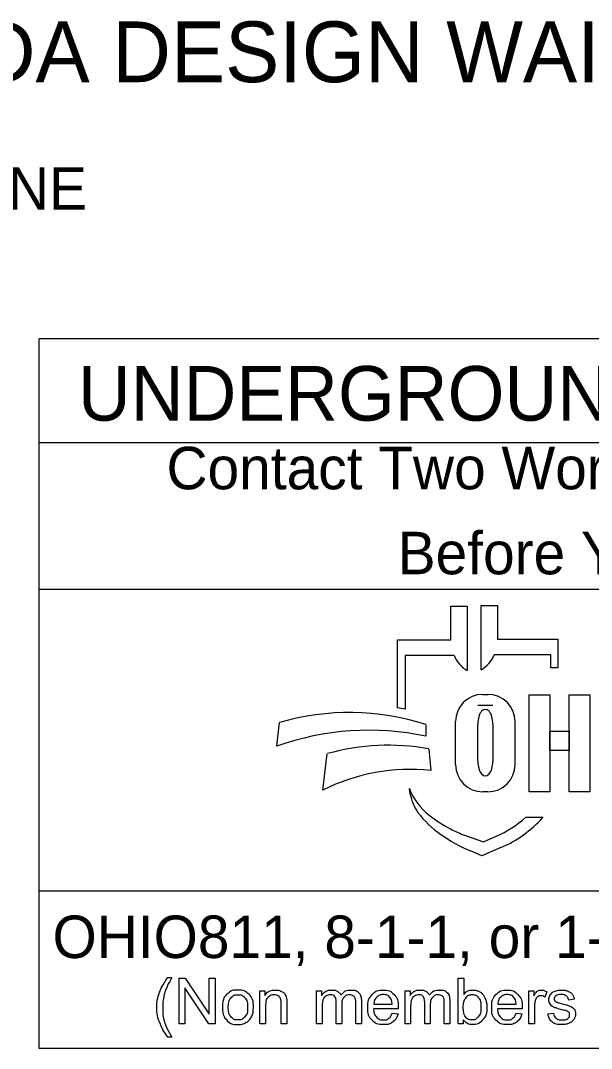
# Model space of a CAD drawing. Extents: x 0 to 34, y 0 to 22.
# Drawn here: x 2.317 to 4.196, y 2.143 to 5.529 of the extents above; entities that cross this region are included whole.
import ezdxf

# ---------------------------------------------------------------- set-up
doc = ezdxf.new("R2010")
doc.units = 0
doc.layers.add('SH_Data', color=7, linetype='Continuous')
doc.layers.add('SH_Text', color=7, linetype='Continuous')

msp = doc.modelspace()

# ---------------------------------------------------------------- linework, layer by layer
at = {"layer": 'SH_Data'}
for p, q in [((2.3775, 2.1428), (2.3775, 4.4803)), ((6.6275, 4.4803), (2.3775, 4.4803)), ((2.3775, 4.1387), (6.6275, 4.1387)), ((2.3775, 3.6553), (6.6275, 3.6553)), ((6.6275, 2.6607), (2.3775, 2.6607)), ((6.6275, 2.1428), (2.3775, 2.1428))]:
    msp.add_line(p, q, dxfattribs=at)
at = {"layer": 'SH_Text'}
for p, q in [((3.7335, 3.4883), (3.7335, 3.5998)), ((3.7335, 3.5998), (3.7872, 3.5998)), ((3.7872, 3.5998), (3.7872, 3.3877)), ((3.8329, 3.39), (3.8329, 3.6021)), ((3.8329, 3.6021), (3.8865, 3.6021)), ((3.8865, 3.6021), (3.8865, 3.4906)), ((3.5576, 3.2644), (3.5576, 3.4883)), ((3.5576, 3.4883), (3.7335, 3.4883)), ((3.8865, 3.4906), (4.0857, 3.4906)), ((4.0857, 3.4906), (4.0857, 3.3968)), ((3.5828, 3.4369), (3.5828, 3.26)), ((3.7439, 3.4369), (3.5828, 3.4369)), ((4.0625, 3.4392), (3.8761, 3.4392)), ((4.0625, 3.3968), (4.0625, 3.4392)), ((4.0857, 3.3968), (4.0625, 3.3968)), ((3.8385, 3.3091), (3.8551, 3.3091)), ((3.8718, 3.2721), (3.822, 3.2721)), ((3.7491, 3.0776), (3.7491, 3.2196)), ((3.9445, 3.2196), (3.9445, 3.0776)), ((3.1602, 3.1381), (3.1696, 3.2162)), ((3.6509, 3.2097), (3.6509, 3.1709)), ((3.822, 3.089), (3.822, 3.2114)), ((3.8718, 3.2114), (3.8718, 3.089)), ((3.6608, 3.1291), (3.6671, 3.0582)), ((3.312, 2.9936), (3.3267, 3.1137)), ((3.5997, 2.9807), (3.5967, 2.9986)), ((3.8551, 2.9882), (3.8385, 2.9882)), ((3.98, 2.9048), (4.0375, 2.9048)), ((3.7816, 2.8444), (3.841, 2.8239)), ((3.841, 2.8239), (3.8821, 2.8417)), ((3.835, 2.7769), (3.7976, 2.7934)), ((3.8983, 2.8044), (3.835, 2.7769))]:
    msp.add_line(p, q, dxfattribs=at)
for points in [[(3.991, 3.3081), (4.0589, 3.3081), (4.0589, 2.9881), (3.991, 2.9881)], [(4.1231, 3.3081), (4.1911, 3.3081), (4.1911, 2.9881), (4.1231, 2.9881)], [(4.0589, 3.1882), (4.1231, 3.1882), (4.1231, 3.1242), (4.0589, 3.1242)]]:
    msp.add_lwpolyline(points, close=True, dxfattribs=at)
for points in [[(2.8021, 2.3766), (2.8153, 2.3766)], [(2.8389, 2.2239), (2.8389, 2.3741), (2.8592, 2.3741), (2.9382, 2.2561), (2.9382, 2.3741), (2.9572, 2.3741), (2.9572, 2.2239), (2.9369, 2.2239), (2.8579, 2.3419), (2.8579, 2.2239), (2.8389, 2.2239)], [(3.7743, 2.2239), (3.7573, 2.2239), (3.7573, 2.3741), (3.7757, 2.3741), (3.7757, 2.3206)], [(3.1048, 2.2239), (3.1048, 2.3328), (3.1214, 2.3328), (3.1214, 2.3173)], [(3.2912, 2.2239), (3.2912, 2.3328), (3.3077, 2.3328), (3.3077, 2.3174)], [(3.5826, 2.2239), (3.5826, 2.3328), (3.5991, 2.3328), (3.5991, 2.3174)], [(3.9904, 2.2239), (3.9904, 2.3328), (4.007, 2.3328), (4.007, 2.3163)], [(4.0495, 2.3293), (4.043, 2.3122)], [(4.1394, 2.3046), (4.1213, 2.3022)], [(3.1233, 2.2833), (3.1233, 2.2239), (3.1048, 2.2239)], [(3.1932, 2.2908), (3.1932, 2.2239), (3.1748, 2.2239), (3.1748, 2.2901)], [(3.3097, 2.2803), (3.3097, 2.2239), (3.2912, 2.2239)], [(3.3743, 2.2871), (3.3743, 2.2239), (3.3559, 2.2239), (3.3559, 2.2946)], [(3.4388, 2.2986), (3.4388, 2.2239), (3.4203, 2.2239), (3.4203, 2.2924)], [(3.56, 2.2736), (3.4788, 2.2736)], [(3.4799, 2.2887), (3.5406, 2.2887)], [(3.601, 2.2803), (3.601, 2.2239), (3.5826, 2.2239)], [(3.6657, 2.2871), (3.6657, 2.2239), (3.6473, 2.2239), (3.6473, 2.2946)], [(3.7301, 2.2986), (3.7301, 2.2239), (3.7117, 2.2239), (3.7117, 2.2924)], [(3.968, 2.2736), (3.8868, 2.2736)], [(3.8879, 2.2887), (3.9486, 2.2887)], [(4.0088, 2.2809), (4.0088, 2.2239), (3.9904, 2.2239)], [(3.5404, 2.2591), (3.5595, 2.2567)], [(3.7743, 2.2375), (3.7743, 2.2239)], [(3.9484, 2.2591), (3.9675, 2.2567)], [(4.053, 2.2564), (4.0712, 2.2593)], [(2.8153, 2.1798), (2.8021, 2.1798)]]:
    msp.add_lwpolyline(points, dxfattribs=at)
for centre, radius, start, end in [((3.8353, 3.4736), 0.0985, 201.9296, 240.7469), ((3.7847, 3.476), 0.0985, 299.2531, 338.0704), ((3.8385, 3.2196), 0.0895, 90, 180), ((3.8551, 3.2196), 0.0895, 0, 90), ((3.4295, 2.4554), 0.8191, 79.2074, 81.0007), ((3.3997, 2.4302), 0.8191, 72.1402, 106.3144), ((3.4628, 2.2991), 0.8919, 77.8238, 109.8274), ((3.5267, 2.4094), 0.7322, 79.44, 105.8467), ((3.5987, 2.4262), 0.6357, 83.8248, 116.8021), ((3.8385, 3.0776), 0.0895, 180, 270), ((3.8551, 3.0776), 0.0895, 270, 0), ((3.7841, 3.0707), 0.2008, 201.0457, 232.5314), ((3.741, 3.0048), 0.1433, 189.6817, 216.0884), ((3.8747, 3.1022), 0.3088, 216.0884, 235.7167), ((3.9766, 3.3219), 0.5173, 232.5314, 241.794), ((3.7387, 3.1722), 0.3602, 293.4582, 312.0712), ((3.7387, 3.1722), 0.401, 293.4582, 317.8286), ((4.0412, 3.3465), 0.6044, 235.7167, 246.2325), ((3.8914, 3.1631), 0.3371, 241.794, 250.9821)]:
    msp.add_arc(centre, radius, start, end, dxfattribs=at)
for centre, start_param, end_param in [((3.8469, 3.2114), 4.712389, 7.853982), ((3.8469, 3.089), 1.570796, 4.712389)]:
    msp.add_ellipse(centre, major_axis=(0, 0.0484), ratio=0.514403, start_param=start_param, end_param=end_param, dxfattribs=at)
for points in [[(2.8021, 2.1798), (2.7869, 2.199), (2.7763, 2.2248), (2.7657, 2.2506), (2.7657, 2.2783), (2.7657, 2.3026), (2.7736, 2.325), (2.7829, 2.3509), (2.8021, 2.3766)], [(2.8153, 2.3766), (2.8029, 2.3553), (2.7989, 2.3462), (2.7927, 2.332), (2.7891, 2.3167), (2.7847, 2.2975), (2.7847, 2.2782), (2.7847, 2.2289), (2.8153, 2.1798)], [(2.9814, 2.2783), (2.9814, 2.3085), (2.9981, 2.3231), (3.0122, 2.3352), (3.0323, 2.3352), (3.0547, 2.3352), (3.069, 2.3205), (3.0832, 2.3058), (3.0832, 2.2799), (3.0832, 2.2589), (3.0769, 2.2469), (3.0706, 2.2348), (3.0586, 2.2282), (3.0466, 2.2215), (3.0323, 2.2215), (3.0095, 2.2215), (2.9954, 2.2362), (2.9814, 2.2508), (2.9814, 2.2783)], [(3.0003, 2.2783), (3.0003, 2.2574), (3.0094, 2.247), (3.0185, 2.2366), (3.0323, 2.2366), (3.046, 2.2366), (3.0551, 2.2471), (3.0642, 2.2575), (3.0642, 2.279), (3.0642, 2.2991), (3.0551, 2.3095), (3.0459, 2.3199), (3.0323, 2.3199), (3.0185, 2.3199), (3.0094, 2.3096), (3.0003, 2.2992), (3.0003, 2.2783)], [(3.1214, 2.3173), (3.1334, 2.3352), (3.156, 2.3352), (3.1659, 2.3352), (3.1741, 2.3316), (3.1823, 2.3281), (3.1864, 2.3224), (3.1905, 2.3166), (3.1922, 2.3087), (3.1932, 2.3036), (3.1932, 2.2908)], [(3.1748, 2.2901), (3.1748, 2.3013), (3.1726, 2.3069), (3.1705, 2.3125), (3.165, 2.3158), (3.1595, 2.3191), (3.1521, 2.3191), (3.1404, 2.3191), (3.1318, 2.3117), (3.1233, 2.3042), (3.1233, 2.2833)], [(3.3077, 2.3174), (3.3128, 2.3254), (3.3214, 2.3303), (3.3299, 2.3352), (3.3407, 2.3352), (3.3528, 2.3352), (3.3606, 2.3301), (3.3683, 2.3251), (3.3715, 2.3161), (3.3844, 2.3352), (3.4051, 2.3352), (3.4213, 2.3352), (3.43, 2.3262), (3.4388, 2.3172), (3.4388, 2.2986)], [(3.3559, 2.2946), (3.3559, 2.3069), (3.3514, 2.313), (3.3469, 2.3191), (3.3366, 2.3191), (3.3288, 2.3191), (3.3222, 2.315), (3.3156, 2.311), (3.3126, 2.3031), (3.3097, 2.2952), (3.3097, 2.2803)], [(3.4203, 2.2924), (3.4203, 2.3035), (3.4185, 2.3083), (3.4168, 2.3132), (3.412, 2.3162), (3.4073, 2.3191), (3.401, 2.3191), (3.3895, 2.3191), (3.3819, 2.3115), (3.3743, 2.3039), (3.3743, 2.2871)], [(3.5595, 2.2567), (3.555, 2.24), (3.5428, 2.2307), (3.5306, 2.2215), (3.5117, 2.2215), (3.4878, 2.2215), (3.4738, 2.2362), (3.4598, 2.2509), (3.4598, 2.2774), (3.4598, 2.3049), (3.474, 2.32), (3.4881, 2.3352), (3.5106, 2.3352), (3.5324, 2.3352), (3.5463, 2.3203), (3.5601, 2.3055), (3.5601, 2.2785), (3.5601, 2.2769), (3.56, 2.2736)], [(3.5406, 2.2887), (3.5394, 2.3025), (3.5337, 2.3094), (3.5249, 2.3201), (3.5108, 2.3201), (3.4981, 2.3201), (3.4894, 2.3115), (3.4808, 2.303), (3.4799, 2.2887)], [(3.5991, 2.3174), (3.6042, 2.3254), (3.6127, 2.3303), (3.6212, 2.3352), (3.6321, 2.3352), (3.6442, 2.3352), (3.6519, 2.3301), (3.6597, 2.3251), (3.6628, 2.3161), (3.6758, 2.3352), (3.6965, 2.3352), (3.7127, 2.3352), (3.7214, 2.3262), (3.7301, 2.3172), (3.7301, 2.2986)], [(3.6473, 2.2946), (3.6473, 2.3069), (3.6428, 2.313), (3.6383, 2.3191), (3.628, 2.3191), (3.6202, 2.3191), (3.6136, 2.315), (3.607, 2.311), (3.604, 2.3031), (3.601, 2.2952), (3.601, 2.2803)], [(3.7117, 2.2924), (3.7117, 2.3035), (3.7099, 2.3083), (3.7081, 2.3132), (3.7034, 2.3162), (3.6987, 2.3191), (3.6923, 2.3191), (3.6809, 2.3191), (3.6733, 2.3115), (3.6657, 2.3039), (3.6657, 2.2871)], [(3.7741, 2.2792), (3.7741, 2.2596), (3.7794, 2.2509), (3.7881, 2.2366), (3.8029, 2.2366), (3.815, 2.2366), (3.8238, 2.2471), (3.8326, 2.2576), (3.8326, 2.2784), (3.8326, 2.2998), (3.8241, 2.3099), (3.8157, 2.3201), (3.8038, 2.3201), (3.7917, 2.3201), (3.7829, 2.3096), (3.7741, 2.299), (3.7741, 2.2792)], [(3.7757, 2.3206), (3.7874, 2.3352), (3.8055, 2.3352), (3.8155, 2.3352), (3.8245, 2.3311), (3.8335, 2.3271), (3.8392, 2.3198), (3.845, 2.3124), (3.8483, 2.3021), (3.8516, 2.2918), (3.8516, 2.28), (3.8516, 2.252), (3.8378, 2.2368), (3.8239, 2.2215), (3.8046, 2.2215), (3.7853, 2.2215), (3.7743, 2.2375)], [(3.9675, 2.2567), (3.963, 2.24), (3.9508, 2.2307), (3.9386, 2.2215), (3.9196, 2.2215), (3.8958, 2.2215), (3.8818, 2.2362), (3.8678, 2.2509), (3.8678, 2.2774), (3.8678, 2.3049), (3.882, 2.32), (3.8961, 2.3352), (3.9186, 2.3352), (3.9404, 2.3352), (3.9543, 2.3203), (3.9681, 2.3055), (3.9681, 2.2785), (3.9681, 2.2769), (3.968, 2.2736)], [(3.9486, 2.2887), (3.9474, 2.3025), (3.9417, 2.3094), (3.9328, 2.3201), (3.9188, 2.3201), (3.9061, 2.3201), (3.8974, 2.3115), (3.8888, 2.303), (3.8879, 2.2887)], [(4.007, 2.3163), (4.0133, 2.3278), (4.0187, 2.3315), (4.0241, 2.3352), (4.0305, 2.3352), (4.0398, 2.3352), (4.0495, 2.3293)], [(4.043, 2.3122), (4.0363, 2.3162), (4.0295, 2.3162), (4.0235, 2.3162), (4.0187, 2.3125), (4.0139, 2.3089), (4.0119, 2.3024), (4.0088, 2.2926), (4.0088, 2.2809)], [(4.1213, 2.3022), (4.1201, 2.3106), (4.1142, 2.3153), (4.1083, 2.3201), (4.0975, 2.3201), (4.0848, 2.3201), (4.0794, 2.3159), (4.0739, 2.3116), (4.0739, 2.306), (4.0739, 2.3024), (4.0762, 2.2995), (4.0785, 2.2966), (4.0833, 2.2946), (4.086, 2.2936), (4.0996, 2.2899), (4.1192, 2.2847), (4.1269, 2.2813), (4.1347, 2.278), (4.1391, 2.2717), (4.1435, 2.2653), (4.1435, 2.2559), (4.1435, 2.2467), (4.1381, 2.2386), (4.1327, 2.2304), (4.1226, 2.226), (4.1124, 2.2215), (4.0996, 2.2215), (4.0784, 2.2215), (4.0672, 2.2303), (4.0561, 2.2391), (4.053, 2.2564)], [(4.0712, 2.2593), (4.0727, 2.2483), (4.0798, 2.2425), (4.0868, 2.2366), (4.0995, 2.2366), (4.1122, 2.2366), (4.1184, 2.2418), (4.1245, 2.247), (4.1245, 2.254), (4.1245, 2.2602), (4.1191, 2.2638), (4.1153, 2.2663), (4.1002, 2.2701), (4.0799, 2.2752), (4.072, 2.2789), (4.0642, 2.2827), (4.0601, 2.2893), (4.0561, 2.2959), (4.0561, 2.3038), (4.0561, 2.3111), (4.0594, 2.3173), (4.0628, 2.3235), (4.0685, 2.3276), (4.0728, 2.3308), (4.0803, 2.333), (4.0877, 2.3352), (4.0962, 2.3352), (4.109, 2.3352), (4.1187, 2.3315), (4.1284, 2.3278), (4.133, 2.3215), (4.1377, 2.3152), (4.1394, 2.3046)], [(3.4788, 2.2736), (3.4799, 2.2557), (3.489, 2.2462), (3.4981, 2.2366), (3.5117, 2.2366), (3.5219, 2.2366), (3.5291, 2.242), (3.5362, 2.2473), (3.5404, 2.2591)], [(3.8868, 2.2736), (3.8879, 2.2557), (3.897, 2.2462), (3.9061, 2.2366), (3.9197, 2.2366), (3.9299, 2.2366), (3.937, 2.242), (3.9442, 2.2473), (3.9484, 2.2591)]]:
    msp.add_open_spline(points, degree=3, dxfattribs=at)

# ---------------------------------------------------------------- texts
for s, height, p in [('ADA DESIGN WAIVERS', 0.2, (1.9944, 5.3256)), ('NONE', 0.14, (1.9944, 4.9056)), ('UNDERGROUND UTILITIES', 0.18, (2.5057, 4.2106)), ('Contact Two Working Days', 0.14, (2.7972, 3.9846)), ('Before You Dig', 0.14, (3.5583, 3.7046)), ('OHIO811, 8-1-1, or 1-800-362-2764', 0.14, (2.422, 2.4406))]:
    msp.add_text(s, height=height, dxfattribs=at).set_placement(p)

doc.saveas('drawing.dxf')
